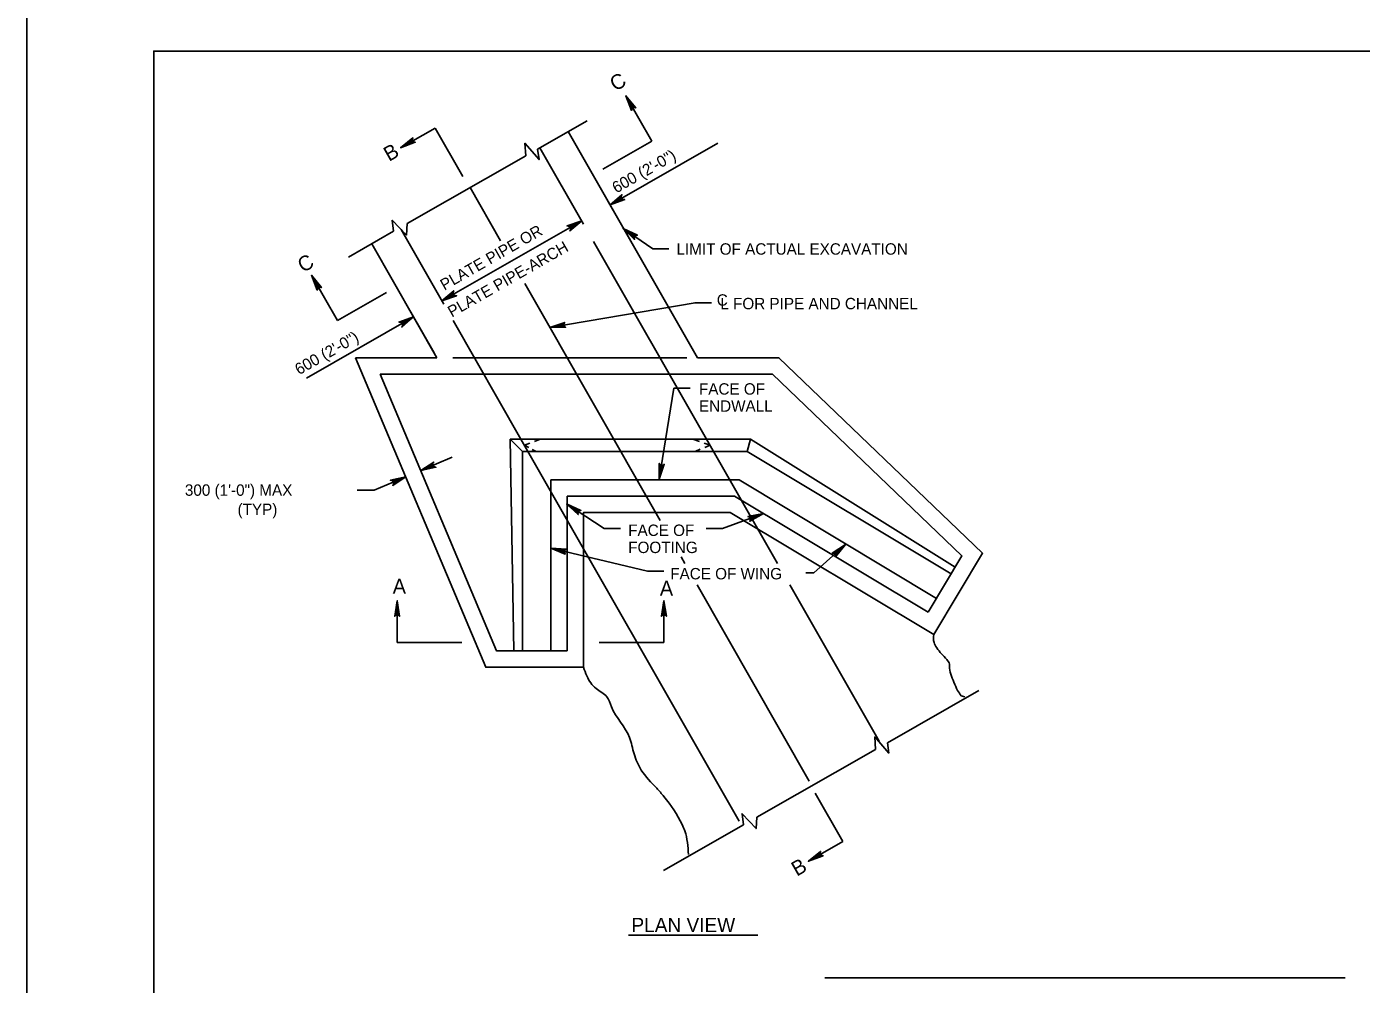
# Model space of a CAD drawing. Extents: x 638454 to 639358, y 297937 to 299125.
# Drawn here: x 638454.1 to 638863.9, y 298229.2 to 298523.2 of the extents above; entities that cross this region are included whole.
import ezdxf

# ---------------------------------------------------------------- set-up
doc = ezdxf.new("R2010")
doc.units = 0
for name, color, linetype in [('1', 7, 'Continuous'), ('2', 7, 'Continuous'), ('3', 7, 'Continuous'), ('PLT-BNDY', 7, 'Continuous')]:
    doc.layers.add(name, color=color, linetype=linetype)

msp = doc.modelspace()

# ---------------------------------------------------------------- linework, layer by layer
at = {"layer": '1'}
msp.add_lwpolyline([(639279.11, 297951.7), (639279.11, 298515.7), (638493.11, 298515.7), (638493.11, 297951.7), (639279.11, 297951.7), (639279.11, 297978.05), (639079.11, 297978.05), (639079.11, 298042.73), (639279.11, 298042.73), (639279.11, 298071.7), (639079.11, 298071.7), (639079.11, 297951.7), (639157.91, 297951.7), (639157.91, 297978.05), (639157.91, 297951.7), (639234.91, 297951.7), (639234.91, 297978.05), (639234.91, 297965.74), (639279.11, 297965.74)], dxfattribs=at)
at = {"layer": '2'}
for p, q in [((638646.03, 298488.1), (638638.08, 298502.01)), ((638568.9, 298486.02), (638579.49, 298492.07)), ((638579.49, 298492.07), (638587.99, 298477.19)), ((638610.97, 298485.63), (638626.18, 298494.32)), ((638660.07, 298421.55), (638620.38, 298491.01)), ((638630.96, 298479.49), (638646.03, 298488.1)), ((638625.08, 298462.61), (638611.69, 298486.05)), ((638666.29, 298487.43), (638633.22, 298468.53)), ((638570.89, 298462.73), (638607.31, 298483.54)), ((638590.22, 298473.78), (638599.56, 298457.44)), ((638639.51, 298457.53), (638632.35, 298470.05)), ((638624.54, 298463.57), (638581.59, 298439.03)), ((638552.95, 298452.48), (638566.76, 298460.37)), ((638582.16, 298438.05), (638569.11, 298460.88)), ((638580.07, 298421.55), (638560.07, 298456.55)), ((638662.84, 298396.55), (638628.17, 298457.21)), ((638631.69, 298451.05), (638631.69, 298451.05)), ((638549.55, 298432.96), (638541.6, 298446.88)), ((638607.03, 298444.36), (638648.59, 298371.63)), ((638564.62, 298441.57), (638549.55, 298432.96)), ((638610.22, 298438.78), (638610.22, 298438.78)), ((638579.2, 298423.06), (638572.04, 298435.59)), ((638605.87, 298396.55), (638585.06, 298432.97)), ((638588.75, 298426.51), (638588.75, 298426.51)), ((638555.07, 298421.55), (638555.07, 298421.55)), ((638685.07, 298421.55), (638685.07, 298421.55)), ((638606.32, 298392.8), (638602.57, 298396.55)), ((638672.89, 298279.26), (638605.87, 298396.55)), ((638684.65, 298358.37), (638662.84, 298396.55)), ((638675.26, 298392.8), (638676.3, 298396.55)), ((638584.75, 298390.99), (638575.08, 298386.92)), ((638655.01, 298360.4), (638656.16, 298358.38)), ((638659.93, 298351.79), (638694.36, 298291.53)), ((638715.84, 298303.8), (638688.37, 298351.86)), ((638567.86, 298334.17), (638567.86, 298346.97)), ((638649.77, 298334.17), (638649.77, 298346.97)), ((638587.71, 298334.17), (638567.86, 298334.17)), ((638629.92, 298334.17), (638649.77, 298334.17)), ((638718.37, 298303.38), (638746.44, 298319.42)), ((638741.03, 298317.76), (638742.14, 298317.48)), ((638678.29, 298280.47), (638714.71, 298301.29)), ((638704.68, 298273), (638696.18, 298287.87)), ((638649.62, 298264.1), (638674.16, 298278.12)), ((638694.09, 298266.95), (638704.68, 298273)), ((638858.86, 298231.15), (638699.12, 298231.15))]:
    msp.add_line(p, q, dxfattribs=at)
for points in [[(638640.83, 298498.35), (638640.46, 298498.34), (638638.08, 298502.01), (638640.83, 298498.35), (638641.12, 298498.25), (638638.08, 298502.01), (638640.06, 298498.11), (638639.86, 298497.81), (638638.08, 298502.01), (638639.79, 298497.49), (638639.86, 298497.81)], [(638573.13, 298487.78), (638572.82, 298487.98), (638568.9, 298486.02), (638573.13, 298487.78), (638573.43, 298487.72), (638568.9, 298486.02), (638572.59, 298488.37), (638572.56, 298488.74), (638568.9, 298486.02), (638572.67, 298489.05), (638572.56, 298488.74)], [(638607.31, 298483.54), (638607.06, 298487.41), (638611.4, 298482.42), (638610.97, 298485.63)], [(638633.22, 298468.53), (638636.86, 298471.62), (638636.67, 298471.23), (638633.22, 298468.53), (638636.66, 298470.86), (638636.77, 298470.56), (638633.22, 298468.53), (638636.97, 298470.31), (638637.29, 298470.13), (638633.22, 298468.53), (638637.73, 298470.1), (638637.29, 298470.13), (638636.97, 298470.31), (638636.77, 298470.56), (638636.66, 298470.86), (638636.67, 298471.23)], [(638566.76, 298460.37), (638566.33, 298463.79), (638570.67, 298459.24), (638570.89, 298462.73)], [(638624.54, 298463.57), (638620.9, 298460.48), (638621.09, 298460.88), (638624.54, 298463.57), (638621.09, 298461.24), (638620.99, 298461.54), (638624.54, 298463.57), (638620.78, 298461.79), (638620.46, 298461.97), (638624.54, 298463.57), (638620.03, 298462.01), (638620.46, 298461.97), (638620.78, 298461.79), (638620.99, 298461.54), (638621.09, 298461.24), (638621.09, 298460.88)], [(638651.31, 298454.99), (638646.31, 298454.99), (638637.22, 298461.23)], [(638640.64, 298458.19), (638640.69, 298458.56), (638637.22, 298461.23), (638640.64, 298458.19), (638640.72, 298457.89), (638637.22, 298461.23), (638640.95, 298458.94), (638641.26, 298459.11), (638637.22, 298461.23), (638641.59, 298459.15), (638641.26, 298459.11)], [(638543.35, 298442.65), (638543.56, 298442.96), (638541.6, 298446.88), (638543.35, 298442.65), (638543.3, 298442.35), (638541.6, 298446.88), (638543.95, 298443.19), (638544.31, 298443.22), (638541.6, 298446.88), (638544.62, 298443.11), (638544.31, 298443.22)], [(638581.59, 298439.03), (638585.23, 298442.12), (638585.04, 298441.73), (638581.59, 298439.03), (638585.04, 298441.36), (638585.14, 298441.06), (638581.59, 298439.03), (638585.35, 298440.81), (638585.67, 298440.63), (638581.59, 298439.03), (638586.1, 298440.6), (638585.67, 298440.63), (638585.35, 298440.81), (638585.14, 298441.06), (638585.04, 298441.36), (638585.04, 298441.73)], [(638664.32, 298438.46), (638659.32, 298438.46), (638614.73, 298430.87)], [(638572.91, 298434.07), (638540.06, 298415.3)], [(638572.91, 298434.07), (638569.27, 298430.98), (638569.46, 298431.38), (638572.91, 298434.07), (638569.47, 298431.74), (638569.36, 298432.04), (638572.91, 298434.07), (638569.16, 298432.29), (638568.84, 298432.47), (638572.91, 298434.07), (638568.4, 298432.51), (638568.84, 298432.47), (638569.16, 298432.29), (638569.36, 298432.04), (638569.47, 298431.74), (638569.46, 298431.38)], [(638619.3, 298431.07), (638619.08, 298431.37), (638614.73, 298430.87), (638619.3, 298431.07), (638619.56, 298430.92), (638614.73, 298430.87), (638619, 298431.82), (638619.1, 298432.17), (638614.73, 298430.87), (638619.31, 298432.42), (638619.1, 298432.17)], [(638555.07, 298421.55), (638580.07, 298421.55)], [(638625.07, 298326.55), (638595.07, 298326.55), (638555.07, 298421.55)], [(638584.95, 298421.55), (638656.74, 298421.55)], [(638660.07, 298421.55), (638685.07, 298421.55), (638747.57, 298361.55), (638732.57, 298336.55)], [(638620.07, 298331.55), (638598.39, 298331.55), (638562.6, 298416.55)], [(638562.6, 298416.55), (638683.06, 298416.55), (638741.23, 298360.7), (638730.85, 298343.41)], [(638657.82, 298412.17), (638652.82, 298412.17), (638648.33, 298384.26)], [(638602.57, 298396.55), (638603.7, 298331.56)], [(638676.3, 298396.55), (638602.57, 298396.55)], [(638608.57, 298395.3), (638606.94, 298394.67), (638608.23, 298393.99)], [(638611.77, 298396.55), (638610.06, 298395.88)], [(638658.66, 298396.55), (638660.63, 298395.84)], [(638662.13, 298395.31), (638663.91, 298394.67), (638662.34, 298394.03)], [(638739.18, 298357.31), (638676.3, 298396.55)], [(638575.08, 298386.92), (638579.06, 298389.55), (638578.82, 298389.18), (638575.08, 298386.92), (638578.77, 298388.81), (638578.84, 298388.5), (638575.08, 298386.92), (638579.02, 298388.23), (638579.31, 298388.02), (638575.08, 298386.92), (638579.74, 298387.93), (638579.31, 298388.02), (638579.02, 298388.23), (638578.84, 298388.5), (638578.77, 298388.81), (638578.82, 298389.18)], [(638737.93, 298355.2), (638675.26, 298392.8), (638606.32, 298392.8), (638606.32, 298331.55)], [(638609.29, 298393.43), (638610.5, 298392.8)], [(638660.92, 298393.45), (638659.3, 298392.8)], [(638649.61, 298388.66), (638649.26, 298388.54), (638648.33, 298384.26), (638649.61, 298388.66), (638649.85, 298388.85), (638648.33, 298384.26), (638648.81, 298388.61), (638648.52, 298388.82), (638648.33, 298384.26), (638648.34, 298389.1), (638648.52, 298388.82)], [(638570.47, 298384.97), (638560.79, 298380.9), (638555.54, 298380.9)], [(638570.47, 298384.97), (638566.48, 298382.34), (638566.72, 298382.72), (638570.47, 298384.97), (638566.77, 298383.08), (638566.7, 298383.39), (638570.47, 298384.97), (638566.53, 298383.66), (638566.23, 298383.88), (638570.47, 298384.97), (638565.8, 298383.97), (638566.23, 298383.88), (638566.53, 298383.66), (638566.7, 298383.39), (638566.77, 298383.08), (638566.72, 298382.72)], [(638733.43, 298347.69), (638672.84, 298384.05), (638615.07, 298384.05), (638615.07, 298331.55)], [(638730.85, 298343.41), (638671.45, 298379.05), (638620.07, 298379.05), (638620.07, 298331.55)], [(638636.41, 298369.09), (638631.41, 298369.09), (638619.88, 298376.67)], [(638623.36, 298373.7), (638623.4, 298374.07), (638619.88, 298376.67), (638623.36, 298373.7), (638623.44, 298373.41), (638619.88, 298376.67), (638623.64, 298374.45), (638623.96, 298374.64), (638619.88, 298376.67), (638624.28, 298374.69), (638623.96, 298374.64)], [(638732.57, 298336.55), (638670.07, 298374.05), (638625.07, 298374.05), (638625.07, 298326.55)], [(638662.7, 298369.09), (638667.7, 298369.09), (638680.31, 298373.69)], [(638675.85, 298372.67), (638676.12, 298372.42), (638680.31, 298373.69), (638675.85, 298372.67), (638675.56, 298372.78), (638680.31, 298373.69), (638676.28, 298371.99), (638676.24, 298371.63), (638680.31, 298373.69), (638676.09, 298371.34), (638676.24, 298371.63)], [(638649.69, 298356.08), (638644.69, 298356.08), (638615, 298363.12)], [(638619.29, 298361.52), (638619.2, 298361.88), (638615, 298363.12), (638619.29, 298361.52), (638619.47, 298361.27), (638615, 298363.12), (638619.3, 298362.33), (638619.53, 298362.61), (638615, 298363.12), (638619.82, 298362.76), (638619.53, 298362.61)], [(638693.32, 298355.54), (638695.82, 298355.54), (638705.51, 298364.21)], [(638701.75, 298361.61), (638702.09, 298361.47), (638705.51, 298364.21), (638701.75, 298361.61), (638701.44, 298361.6), (638705.51, 298364.21), (638702.4, 298361.14), (638702.5, 298360.79), (638705.51, 298364.21), (638702.46, 298360.46), (638702.5, 298360.79)], [(638567.29, 298342.43), (638567.62, 298342.6), (638567.86, 298346.97), (638567.29, 298342.43), (638567.09, 298342.2), (638567.86, 298346.97), (638568.08, 298342.6), (638568.4, 298342.45), (638567.86, 298346.97), (638568.62, 298342.2), (638568.4, 298342.45)], [(638649.2, 298342.43), (638649.53, 298342.6), (638649.77, 298346.97), (638649.2, 298342.43), (638649, 298342.2), (638649.77, 298346.97), (638649.98, 298342.6), (638650.31, 298342.45), (638649.77, 298346.97), (638650.53, 298342.2), (638650.31, 298342.45)], [(638714.71, 298301.29), (638714.47, 298305.16), (638718.8, 298300.17), (638718.37, 298303.38)], [(638674.16, 298278.12), (638673.74, 298281.54), (638678.07, 298276.99), (638678.29, 298280.47)], [(638697.75, 298269.69), (638697.76, 298269.32), (638694.09, 298266.95), (638697.75, 298269.69), (638697.85, 298269.98), (638694.09, 298266.95), (638697.99, 298268.92), (638698.29, 298268.72), (638694.09, 298266.95), (638698.61, 298268.65), (638698.29, 298268.72)]]:
    msp.add_lwpolyline(points, dxfattribs=at)
for points in [[(638732.57, 298336.55), (638732.68, 298334.17), (638733.52, 298332.5), (638736.58, 298328.89), (638737.41, 298327.5), (638737.41, 298326.94), (638738.8, 298321.93), (638739.92, 298319.42), (638741.03, 298317.76)], [(638625.07, 298326.55), (638626.11, 298323.88), (638628.9, 298319.98), (638632.24, 298317.48), (638633.63, 298314.42), (638639.19, 298304.96), (638640.58, 298299.95), (638642.81, 298294.94), (638647.54, 298289.37), (638649.76, 298286.87), (638655.33, 298278.25), (638656.16, 298276.3), (638657.28, 298269.06)]]:
    msp.add_spline(points, degree=3, dxfattribs=at)
at = {"layer": '3'}
msp.add_line((638638.84, 298244.23), (638678.61, 298244.23), dxfattribs=at)
at = {"layer": 'PLT-BNDY'}
msp.add_lwpolyline([(638454.11, 298530.7), (639295.11, 298530.7), (639295.11, 297936.7), (638454.11, 297936.7)], close=True, dxfattribs=at)

# ---------------------------------------------------------------- texts
at = {"layer": '3'}
for s, height, rotation, p in [('C', 4.55, 29.7453, (638634.81, 298503.23)), ('B', 4.55, 29.7453, (638565.35, 298481.67)), ('600 (2\'-0")', 3.5, 29.7452, (638635.13, 298471.95)), ('PLATE PIPE OR', 3.5, 29.7445, (638582.34, 298442.1)), ('PLATE PIPE-ARCH', 3.5, 29.7445, (638584.64, 298433.86)), ('C', 4.55, 29.7442, (638538.94, 298447.55)), ('600 (2\'-0")', 3.5, 29.7453, (638537.72, 298416.17)), ('B', 4.55, 29.7437, (638690.55, 298262.22))]:
    msp.add_text(s, height=height, rotation=rotation, dxfattribs=at).set_placement(p)
for s, height, p in [('LIMIT OF ACTUAL EXCAVATION', 3.5, (638653.62, 298453.2)), ('C', 3.5, (638665.98, 298437.54)), ('L FOR PIPE AND CHANNEL', 3.5, (638667.08, 298436.44)), ('FACE OF', 3.5, (638660.51, 298410.23)), ('ENDWALL', 3.5, (638660.51, 298404.98)), ('300 (1\'-0") MAX', 3.5, (638502.68, 298379.18)), ('(TYP)', 3.5, (638518.85, 298373.27)), ('FACE OF', 3.5, (638638.79, 298366.84)), ('FOOTING', 3.5, (638638.79, 298361.59)), ('FACE OF WING', 3.5, (638651.7, 298353.51)), ('A', 4.55, (638566.49, 298349.15)), ('A', 4.55, (638648.51, 298348.54)), ('PLAN VIEW', 4.375, (638639.78, 298245.22))]:
    msp.add_text(s, height=height, dxfattribs=at).set_placement(p)

doc.saveas('drawing.dxf')
